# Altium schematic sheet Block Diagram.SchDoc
size 431 x 279 mm; Date: Not shown in title block; ApprovedBy: Not shown in title block; CheckedBy: Not shown in title block; Author: Not shown in title block; CompanyName: Not shown in title block; Engineer: Not shown in title block; Organization: Not shown in title block; Address1: Not shown in title block; Address2: Not shown in title block; Address3: Not shown in title block; Address4: Not shown in title block; DocumentNumber: 1; Revision: Use project parameter SCH_Rev; SheetNumber: 2; SheetTotal: 3; PageSetup: Record=PageOptions¦CenterHorizontal=True¦CenterVertical=True¦PrintScale=0.96¦XCorrection=1.00¦YCorrection=1.00¦PrintKind=0¦BorderSize=5000000¦LeftOffset=0¦BottomOffset=0¦Orientation=2¦PaperLength=1000¦PaperWidth=1000¦Scale=100¦PaperSource=15¦PrintQuality=-3¦MediaType=1¦DitherType=10¦PrintScaleMode=1¦PaperKind=11x17¦PaperIndex=17
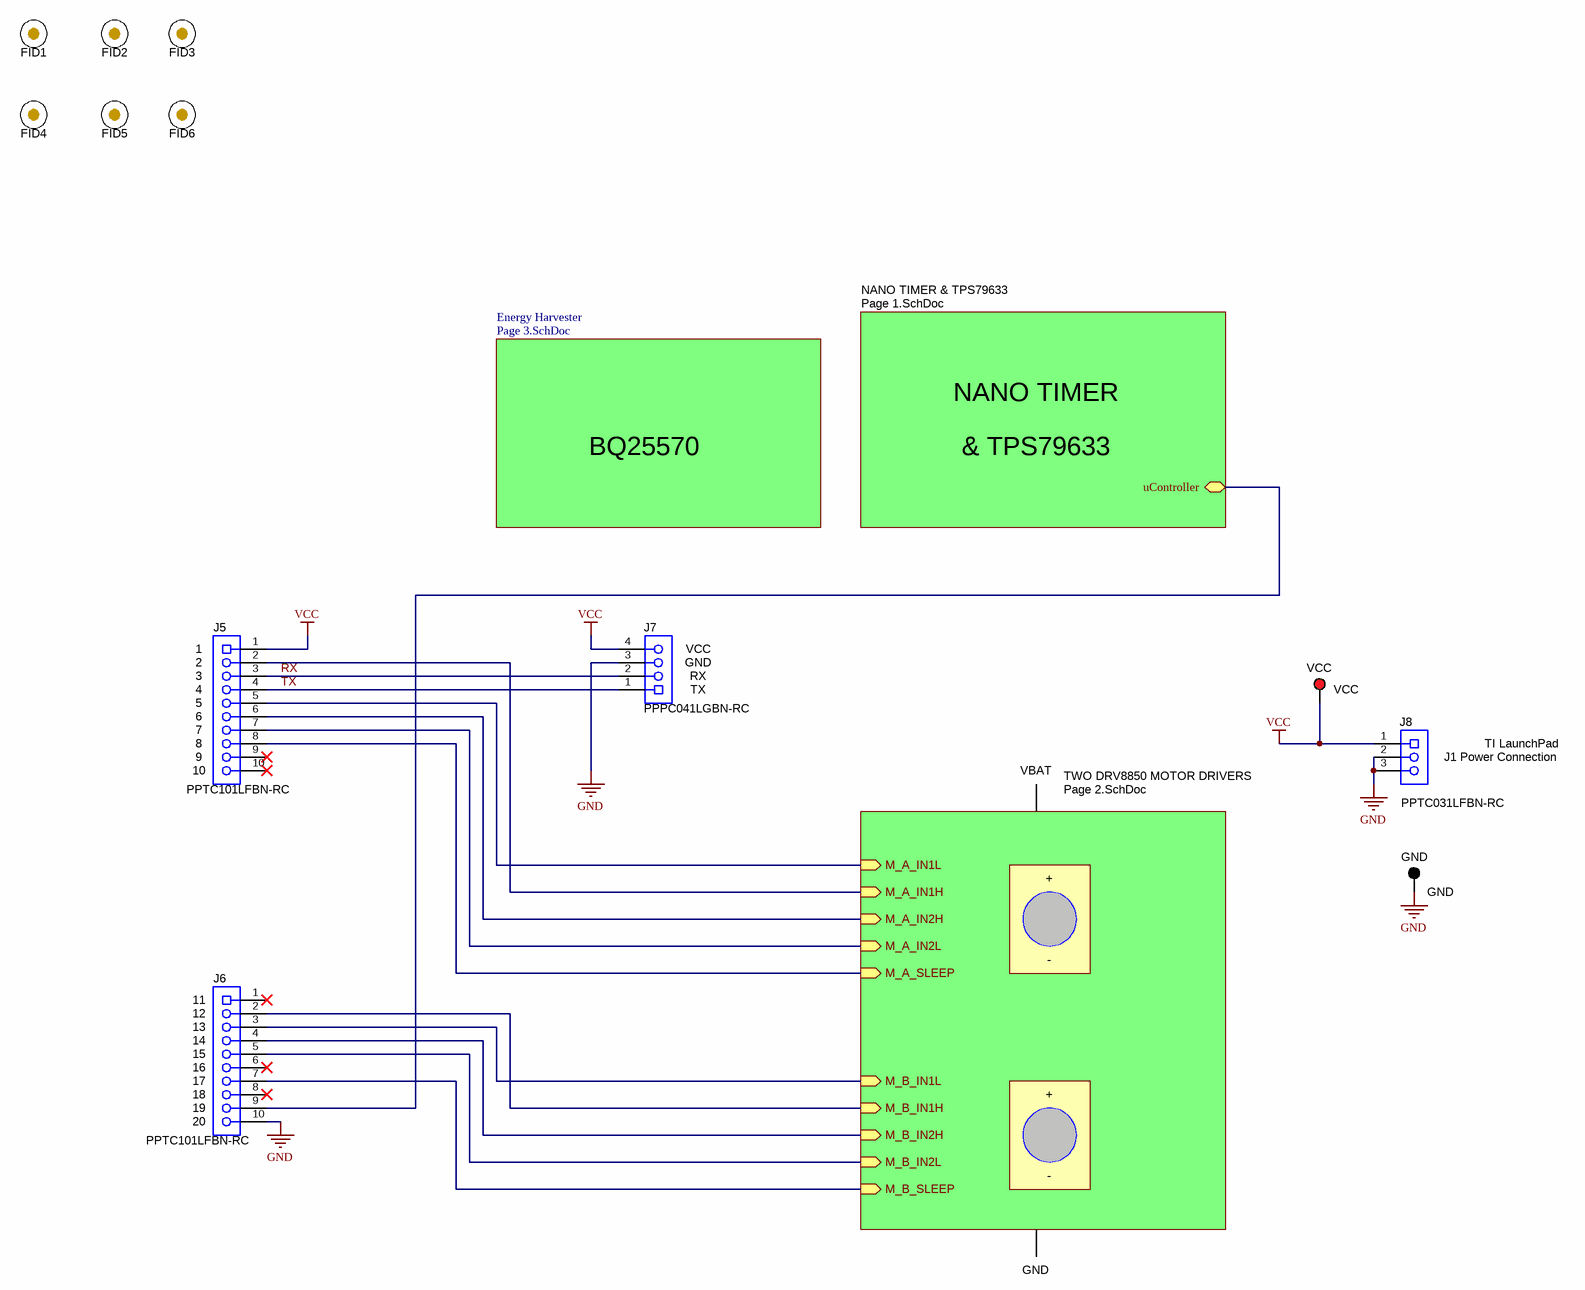
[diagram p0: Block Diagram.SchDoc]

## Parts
FID1  Fiducial  [Fiducial10-20]  (value not drawn)
FID2  Fiducial  [Fiducial10-20]  (value not drawn)
FID3  Fiducial  [Fiducial10-20]  (value not drawn)
FID4  Fiducial  [Fiducial10-20]  (value not drawn)
FID5  Fiducial  [Fiducial10-20]  (value not drawn)
FID6  Fiducial  [Fiducial10-20]  (value not drawn)
GND  5001  [Keystone5001]  (value not drawn)
J5  PPTC101LFBN-RC  [CONN_PPTC101LFBN-RC]
J6  PPTC101LFBN-RC  [CONN_PPTC101LFBN-RC]
J7  PPPC041LGBN-RC  [SULLINS_PPPC041LGBN-RC]
J8  PPTC031LFBN-RC  [Sullins_PPTC031LFBN-RC]
VCC  5000  [Keystone5000]  (value not drawn)

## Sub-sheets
Energy Harvester = Page 3.SchDoc: no entries
NANO TIMER & TPS79633 = Page 1.SchDoc: uController (bidir)
TWO DRV8850 MOTOR DRIVERS = Page 2.SchDoc: M_A_IN1L (in), M_A_IN1H (in), M_A_IN2H (in), M_A_IN2L (in), M_A_SLEEP (in), M_B_IN1H (in), M_B_IN1L (in), M_B_IN2H (in), M_B_IN2L (in), M_B_SLEEP (in)

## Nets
GND: GND.1 J6.10 J7.3 J8.2 J8.3
VCC: J5.1 J7.4 J8.1 VCC.1
RX: J5.3 J7.2
TX: J5.4 J7.1
NetJ5_2: J5.2 ; sheet TWO DRV8850 MOTOR DRIVERS/M_A_IN1H
NetJ5_5: J5.5 ; sheet TWO DRV8850 MOTOR DRIVERS/M_A_IN1L
NetJ5_6: J5.6 ; sheet TWO DRV8850 MOTOR DRIVERS/M_A_IN2H
NetJ5_7: J5.7 ; sheet TWO DRV8850 MOTOR DRIVERS/M_A_IN2L
NetJ5_8: J5.8 ; sheet TWO DRV8850 MOTOR DRIVERS/M_A_SLEEP
NetJ6_2: J6.2 ; sheet TWO DRV8850 MOTOR DRIVERS/M_B_IN1H
NetJ6_3: J6.3 ; sheet TWO DRV8850 MOTOR DRIVERS/M_B_IN1L
NetJ6_4: J6.4 ; sheet TWO DRV8850 MOTOR DRIVERS/M_B_IN2H
NetJ6_5: J6.5 ; sheet TWO DRV8850 MOTOR DRIVERS/M_B_IN2L
NetJ6_7: J6.7 ; sheet TWO DRV8850 MOTOR DRIVERS/M_B_SLEEP
NetJ6_9: J6.9 ; sheet NANO TIMER & TPS79633/uController

Not connected (* = marked no-connect by the designer): J5 9* 10*; J6 1* 6* 8*

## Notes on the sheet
- NANO TIMER
- BQ25570
- & TPS79633
- (near J5) 1
- (near J5) 2
- (near J5) 3
- (near J7) RX
- (near J7) GND
- (near J7) VCC
- (near J5) 4
- (near J5) 5
- (near J5) 6
- (near J5) 7
- (near J5) 8
- (near J7) TX
- (near VCC) VCC
- TI LaunchPad
- (near J5) 9
- (near J5) 10
- VBAT
- (near J8) J1 Power Connection
- +
- (near GND) GND
- (near J6) 11
- (near J6) 12
- -
- (near J6) 13
- (near J6) 14
- (near J6) 15
- (near J6) 16
- (near J6) 17
- (near J6) 18
- (near J6) 19
- (near J6) 20
- GND

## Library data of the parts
FID1-FID6 = Fiducial: Fiducial mark.  There is nothing to buy or mount.; SymbolCreator: codlsc
GND = 5001: Test Point, Miniature, Black, TH; Manufacturer: Keystone; CompType: Test Point Loop; U/M: EA
J5 J6 = PPTC101LFBN-RC: Receptacle 100mil 10x1, Tin, TH; Manufacturer: Sullins Connector Solutions; SymbolCreator: a0411947; U/M: EA
J7 = PPPC041LGBN-RC: Receptacle, 100mil, 4x1, Gold, R/A, TH; Manufacturer: Sullins Connector Solutions; SymbolCreator: a0411947; U/M: EA
J8 = PPTC031LFBN-RC: Receptacle, 100mil, 3X1, TH; Manufacturer: Sullins Connector Solutions; SymbolCreator: a0412235; U/M: EA
VCC = 5000: Test Point, Miniature, Red, TH; Manufacturer: Keystone; CompType: Test Point Loop; U/M: EA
